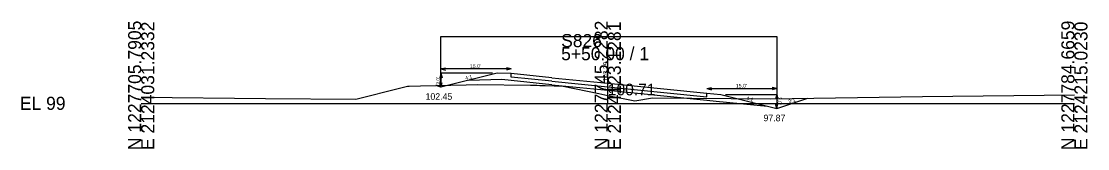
# Model space of a CAD drawing. Extents: x 2118382 to 2129610, y 1213030 to 1222578.
# Drawn here: x 2118381.9 to 2118610.4, y 1216030.1 to 1216057.3 of the extents above; entities that cross this region are included whole.
import ezdxf

# ---------------------------------------------------------------- set-up
doc = ezdxf.new("R2010")
doc.units = 0
for name, color, linetype in [('XS_CELL', 7, 'Continuous'), ('XS_M_DITCH', 7, 'Continuous'), ('XS_P_FINISHED_GRADE', 7, 'Continuous'), ('XS_P_FINISHED_GRADE_ELEV_TX', 7, 'Continuous'), ('XS_P_SUBGRADE_GRANULAR', 7, 'Continuous'), ('XS_P_SUBGRADE_PAVEMENT', 7, 'Continuous'), ('XS_P_TX_CLEARZONE', 7, 'Continuous'), ('XS_P_TX_DCH', 7, 'Continuous'), ('XS_P_TX_FS_BS', 7, 'Continuous'), ('XS_X_GROUND', 7, 'Continuous'), ('XS_X_GROUND_TX', 7, 'Continuous')]:
    doc.layers.add(name, color=color, linetype=linetype)

msp = doc.modelspace()

# ---------------------------------------------------------------- linework, layer by layer
at = {"layer": 'XS_CELL'}
for p, q in [((2118507.6, 1216039.8), (2118507.6, 1216051.82)), ((2118407.6, 1216039.8), (2118507.6, 1216039.8)), ((2118507.6, 1216039.8), (2118607.6, 1216039.8))]:
    msp.add_line(p, q, dxfattribs=at)
at = {"layer": 'XS_M_DITCH'}
for p, q in [((2118471.84, 1216043.26), (2118471.84, 1216054.09)), ((2118471.84, 1216054.09), (2118543.82, 1216054.09)), ((2118543.82, 1216054.09), (2118543.82, 1216038.67))]:
    msp.add_line(p, q, dxfattribs=at)
at = {"layer": 'XS_P_FINISHED_GRADE'}
for p, q in [((2118483.86, 1216046.26), (2118471.84, 1216043.26)), ((2118486.86, 1216046.17), (2118483.86, 1216046.26)), ((2118495.6, 1216045.29), (2118486.86, 1216046.17)), ((2118495.6, 1216045.29), (2118507.6, 1216044.09)), ((2118471.84, 1216043.26), (2118470.78, 1216043.61)), ((2118507.6, 1216044.09), (2118519.6, 1216042.89)), ((2118519.6, 1216042.89), (2118528.79, 1216041.97)), ((2118528.79, 1216041.97), (2118531.8, 1216041.67)), ((2118531.8, 1216041.67), (2118543.82, 1216038.67)), ((2118543.82, 1216038.67), (2118550.47, 1216040.89))]:
    msp.add_line(p, q, dxfattribs=at)
at = {"layer": 'XS_P_SUBGRADE_GRANULAR'}
for p, q in [((2118484.86, 1216044.87), (2118477.72, 1216044.72)), ((2118486.86, 1216044.67), (2118484.86, 1216044.87)), ((2118495.6, 1216043.79), (2118486.86, 1216044.67)), ((2118495.6, 1216043.79), (2118507.6, 1216042.59)), ((2118507.6, 1216042.59), (2118519.6, 1216041.39)), ((2118519.6, 1216041.39), (2118528.79, 1216040.47)), ((2118528.79, 1216040.47), (2118530.79, 1216040.27)), ((2118530.79, 1216040.27), (2118541.83, 1216039.17))]:
    msp.add_line(p, q, dxfattribs=at)
at = {"layer": 'XS_P_SUBGRADE_PAVEMENT'}
for p, q in [((2118486.86, 1216045.42), (2118486.86, 1216046.17)), ((2118495.6, 1216044.54), (2118486.86, 1216045.42)), ((2118495.6, 1216044.54), (2118507.6, 1216043.34)), ((2118507.6, 1216043.34), (2118519.6, 1216042.14)), ((2118519.6, 1216042.14), (2118528.79, 1216041.22)), ((2118528.79, 1216041.22), (2118528.79, 1216041.97))]:
    msp.add_line(p, q, dxfattribs=at)
at = {"layer": 'XS_P_TX_CLEARZONE'}
for p, q in [((2118471.84, 1216047.17), (2118472.84, 1216047.42)), ((2118471.84, 1216047.17), (2118472.84, 1216046.92)), ((2118486.86, 1216047.17), (2118471.84, 1216047.17)), ((2118486.86, 1216047.17), (2118485.86, 1216047.42)), ((2118486.86, 1216047.17), (2118485.86, 1216046.92)), ((2118471.84, 1216046.26), (2118471.59, 1216045.26)), ((2118471.84, 1216046.26), (2118472.09, 1216045.26)), ((2118471.84, 1216046.26), (2118471.84, 1216043.26)), ((2118482.86, 1216046.26), (2118471.84, 1216046.26)), ((2118471.84, 1216043.26), (2118471.59, 1216044.26)), ((2118471.84, 1216043.26), (2118472.09, 1216044.26)), ((2118528.79, 1216042.97), (2118529.8, 1216043.22)), ((2118528.79, 1216042.97), (2118529.8, 1216042.72)), ((2118528.79, 1216042.97), (2118543.82, 1216042.97)), ((2118543.82, 1216042.97), (2118542.82, 1216043.22)), ((2118543.82, 1216042.97), (2118542.82, 1216042.72)), ((2118532.8, 1216041.67), (2118543.82, 1216041.67)), ((2118543.82, 1216041.67), (2118543.57, 1216040.67)), ((2118543.82, 1216041.67), (2118543.82, 1216038.67)), ((2118543.82, 1216041.67), (2118544.07, 1216040.67)), ((2118543.82, 1216038.67), (2118543.57, 1216039.67)), ((2118543.82, 1216038.67), (2118544.07, 1216039.67))]:
    msp.add_line(p, q, dxfattribs=at)
at = {"layer": 'XS_X_GROUND'}
for p, q in [((2118453.61, 1216040.69), (2118463.26, 1216043.14)), ((2118463.26, 1216043.14), (2118464.69, 1216043.49)), ((2118464.69, 1216043.49), (2118465, 1216043.49)), ((2118465, 1216043.49), (2118467.48, 1216043.54)), ((2118467.48, 1216043.54), (2118477.26, 1216043.75)), ((2118477.26, 1216043.75), (2118479.66, 1216043.81)), ((2118479.66, 1216043.81), (2118491, 1216043.69)), ((2118491, 1216043.69), (2118492.36, 1216043.67)), ((2118492.36, 1216043.67), (2118493.06, 1216043.65)), ((2118493.06, 1216043.65), (2118494.18, 1216043.6)), ((2118494.18, 1216043.6), (2118498.04, 1216043.44)), ((2118498.04, 1216043.44), (2118505.65, 1216041.91)), ((2118407.6, 1216041.13), (2118434.21, 1216040.85)), ((2118434.21, 1216040.85), (2118453.61, 1216040.69)), ((2118505.65, 1216041.91), (2118507.6, 1216041.51)), ((2118507.6, 1216041.51), (2118513.42, 1216040.33)), ((2118513.42, 1216040.33), (2118517.18, 1216040.96)), ((2118517.18, 1216040.96), (2118542.44, 1216040.77)), ((2118542.44, 1216040.77), (2118575.04, 1216041.25)), ((2118575.04, 1216041.25), (2118607.6, 1216041.64))]:
    msp.add_line(p, q, dxfattribs=at)

# ---------------------------------------------------------------- texts
at = {"layer": 'XS_CELL'}
for s, p in [('N 1227705.7905', (2118407.6, 1216029.8)), ('E 2124031.2332', (2118410.4, 1216029.8)), ('N 1227745.2282', (2118507.6, 1216029.8)), ('E 2124123.1281', (2118510.4, 1216029.8)), ('N 1227784.6659', (2118607.6, 1216029.8)), ('E 2124215.0230', (2118610.4, 1216029.8))]:
    msp.add_text(s, height=2.8, rotation=90, dxfattribs=at).set_placement(p)
for s, p in [('S826', (2118497.6, 1216051.82)), ('5+50.00 / 1', (2118497.6, 1216049.02)), ('EL 99', (2118381.6, 1216038.4))]:
    msp.add_text(s, height=2.8, dxfattribs=at).set_placement(p)
at = {"layer": 'XS_P_FINISHED_GRADE_ELEV_TX'}
msp.add_text(' 103.29', height=1, rotation=90, dxfattribs=at).set_placement((2118507.6, 1216044.09))
at = {"layer": 'XS_P_TX_CLEARZONE'}
for p in [(2118478.06, 1216047.37), (2118535.04, 1216043.17)]:
    msp.add_text("15.0'", height=0.8, dxfattribs=at).set_placement(p)
for rotation, p in [(90, (2118471.64, 1216043.73)), (270, (2118544.02, 1216041.2))]:
    msp.add_text("3.0'", height=0.8, rotation=rotation, dxfattribs=at).set_placement(p)
at = {"layer": 'XS_P_TX_DCH'}
for s, p in [('102.45', (2118468.54, 1216040.56)), ('97.87', (2118540.97, 1216035.97))]:
    msp.add_text(s, height=1.4, dxfattribs=at).set_placement(p)
at = {"layer": 'XS_P_TX_FS_BS'}
for s, rotation, p in [('4:1', 14.0167, (2118477.14, 1216044.78)), ('4:1', 345.9871, (2118537.2, 1216040.53)), ('3:1', 18.4052, (2118546.44, 1216039.75))]:
    msp.add_text(s, height=0.8, rotation=rotation, dxfattribs=at).set_placement(p)
at = {"layer": 'XS_X_GROUND_TX'}
msp.add_text('100.71', height=2.5, dxfattribs=at).set_placement((2118507.6, 1216041.51))

doc.saveas('drawing.dxf')
